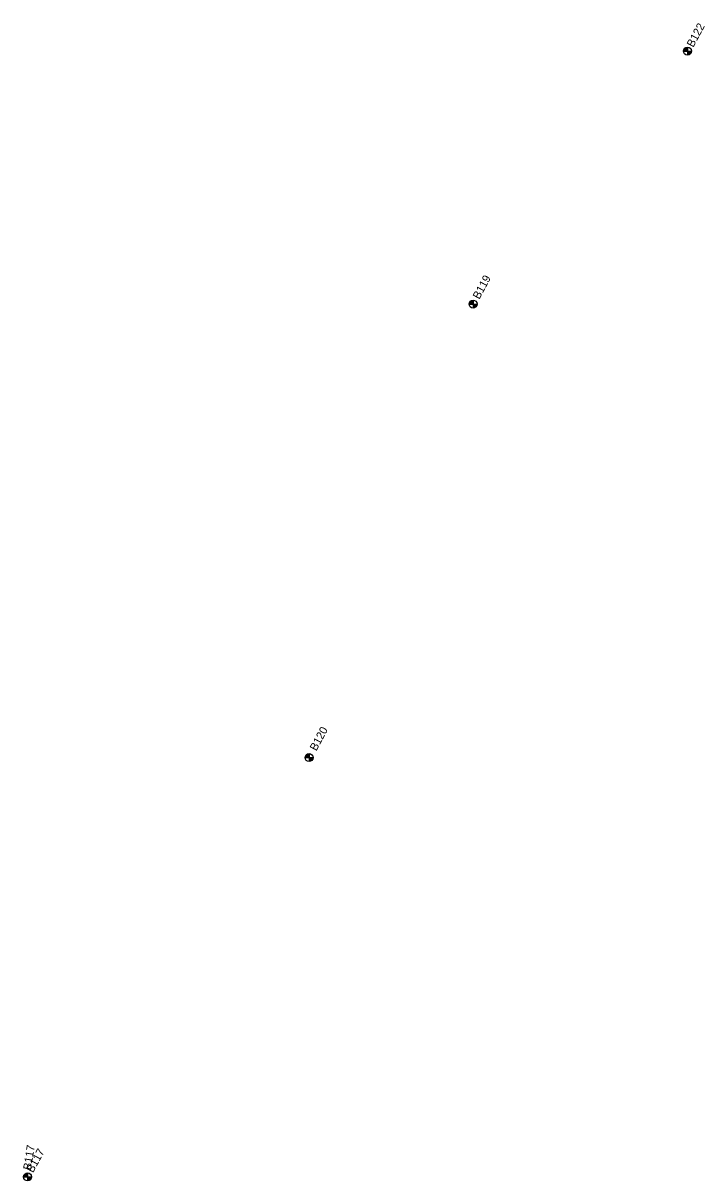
# Model space of a CAD drawing. Extents: x 335726 to 369746, y 119154 to 200788.
# Drawn here: x 355388 to 356240, y 193761 to 195207 of the extents above; entities that cross this region are included whole.
import ezdxf

# ---------------------------------------------------------------- set-up
doc = ezdxf.new("R2010")
doc.units = 0
for name, color, linetype in [('E_SOIL_BORE1 [KAPUR_CADDS_LEVELS]', 7, 'Continuous'), ('E_SOIL_BORE2 [KAPUR_CADDS_LEVELS]', 7, 'Continuous'), ('P_MARK', 7, 'Continuous')]:
    doc.layers.add(name, color=color, linetype=linetype)

msp = doc.modelspace()

# ---------------------------------------------------------------- linework, layer by layer
at = {"layer": 'P_MARK'}
for p, q in [((356213, 195172.4), (356223, 195172.4)), ((356218, 195177.4), (356218, 195167.4)), ((355945.1, 194856.3), (355955.1, 194856.3)), ((355950.1, 194861.3), (355950.1, 194851.3)), ((355740.3, 194289.7), (355750.3, 194289.7)), ((355745.3, 194294.7), (355745.3, 194284.7)), ((355388.6, 193765.9), (355398.6, 193765.9)), ((355393.6, 193770.9), (355393.6, 193760.9))]:
    msp.add_line(p, q, dxfattribs=at)
for centre in [(356218, 195172.4), (355950.1, 194856.3), (355745.3, 194289.7), (355393.6, 193765.9)]:
    msp.add_circle(centre, 5, dxfattribs=at)
for centre, radius, start, end in [((356218, 195172.4), 4.5, 89.9869, 179.9869), ((356218, 195172.4), 4, 89.9869, 179.9869), ((356218, 195172.4), 3.5, 89.9869, 179.9869), ((356218, 195172.4), 3, 89.9869, 179.9869), ((356218, 195172.4), 2.5, 89.9869, 179.9869), ((356218, 195172.4), 2, 89.9869, 179.9869), ((356218, 195172.4), 1.5, 89.9869, 179.9869), ((356218, 195172.4), 1, 89.9869, 179.9869), ((356218, 195172.4), 0.5, 89.9869, 179.9869), ((356218, 195172.4), 4.5, 269.9869, 359.9869), ((356218, 195172.4), 4, 269.9869, 359.9869), ((356218, 195172.4), 3.5, 269.9869, 359.9869), ((356218, 195172.4), 3, 269.9869, 359.9869), ((356218, 195172.4), 2.5, 269.9869, 359.9869), ((356218, 195172.4), 2, 269.9869, 359.9869), ((356218, 195172.4), 1.5, 269.9869, 359.9869), ((356218, 195172.4), 1, 269.9869, 359.9869), ((356218, 195172.4), 0.5, 269.9869, 359.9869), ((355950.1, 194856.3), 4.5, 89.9869, 179.9869), ((355950.1, 194856.3), 4, 89.9869, 179.9869), ((355950.1, 194856.3), 3.5, 89.9869, 179.9869), ((355950.1, 194856.3), 3, 89.9869, 179.9869), ((355950.1, 194856.3), 2.5, 89.9869, 179.9869), ((355950.1, 194856.3), 2, 89.9869, 179.9869), ((355950.1, 194856.3), 1.5, 89.9869, 179.9869), ((355950.1, 194856.3), 1, 89.9869, 179.9869), ((355950.1, 194856.3), 0.5, 89.9869, 179.9869), ((355950.1, 194856.3), 4.5, 269.9869, 359.9869), ((355950.1, 194856.3), 4, 269.9869, 359.9869), ((355950.1, 194856.3), 3.5, 269.9869, 359.9869), ((355950.1, 194856.3), 3, 269.9869, 359.9869), ((355950.1, 194856.3), 2.5, 269.9869, 359.9869), ((355950.1, 194856.3), 2, 269.9869, 359.9869), ((355950.1, 194856.3), 1.5, 269.9869, 359.9869), ((355950.1, 194856.3), 1, 269.9869, 359.9869), ((355950.1, 194856.3), 0.5, 269.9869, 359.9869), ((355745.3, 194289.7), 4.5, 89.9869, 179.9869), ((355745.3, 194289.7), 4, 89.9869, 179.9869), ((355745.3, 194289.7), 3.5, 89.9869, 179.9869), ((355745.3, 194289.7), 3, 89.9869, 179.9869), ((355745.3, 194289.7), 2.5, 89.9869, 179.9869), ((355745.3, 194289.7), 2, 89.9869, 179.9869), ((355745.3, 194289.7), 1.5, 89.9869, 179.9869), ((355745.3, 194289.7), 1, 89.9869, 179.9869), ((355745.3, 194289.7), 0.5, 89.9869, 179.9869), ((355745.3, 194289.7), 4.5, 269.9869, 359.9869), ((355745.3, 194289.7), 4, 269.9869, 359.9869), ((355745.3, 194289.7), 3.5, 269.9869, 359.9869), ((355745.3, 194289.7), 3, 269.9869, 359.9869), ((355745.3, 194289.7), 2.5, 269.9869, 359.9869), ((355745.3, 194289.7), 2, 269.9869, 359.9869), ((355745.3, 194289.7), 1.5, 269.9869, 359.9869), ((355745.3, 194289.7), 1, 269.9869, 359.9869), ((355745.3, 194289.7), 0.5, 269.9869, 359.9869), ((355393.6, 193765.9), 4.5, 89.9869, 179.9869), ((355393.6, 193765.9), 4, 89.9869, 179.9869), ((355393.6, 193765.9), 3.5, 89.9869, 179.9869), ((355393.6, 193765.9), 3, 89.9869, 179.9869), ((355393.6, 193765.9), 2.5, 89.9869, 179.9869), ((355393.6, 193765.9), 2, 89.9869, 179.9869), ((355393.6, 193765.9), 1.5, 89.9869, 179.9869), ((355393.6, 193765.9), 1, 89.9869, 179.9869), ((355393.6, 193765.9), 0.5, 89.9869, 179.9869), ((355393.6, 193765.9), 4.5, 269.9869, 359.9869), ((355393.6, 193765.9), 4, 269.9869, 359.9869), ((355393.6, 193765.9), 3.5, 269.9869, 359.9869), ((355393.6, 193765.9), 3, 269.9869, 359.9869), ((355393.6, 193765.9), 2.5, 269.9869, 359.9869), ((355393.6, 193765.9), 2, 269.9869, 359.9869), ((355393.6, 193765.9), 1.5, 269.9869, 359.9869), ((355393.6, 193765.9), 1, 269.9869, 359.9869), ((355393.6, 193765.9), 0.5, 269.9869, 359.9869)]:
    msp.add_arc(centre, radius, start, end, dxfattribs=at)

# ---------------------------------------------------------------- texts
at = {"layer": 'E_SOIL_BORE1 [KAPUR_CADDS_LEVELS]'}
for s, rotation, p in [('B122', 61.5935, (356225.2, 195176.3)), ('B117', 80.9358, (355397.8, 193774))]:
    msp.add_text(s, height=10, rotation=rotation, dxfattribs=at).set_placement(p)
at = {"layer": 'E_SOIL_BORE2 [KAPUR_CADDS_LEVELS]'}
for s, p in [('B119', (355957.9, 194861.5)), ('B120', (355754.3, 194297.2)), ('B117', (355400.4, 193770.2))]:
    msp.add_text(s, height=10, rotation=61.5935, dxfattribs=at).set_placement(p)

doc.saveas('drawing.dxf')
